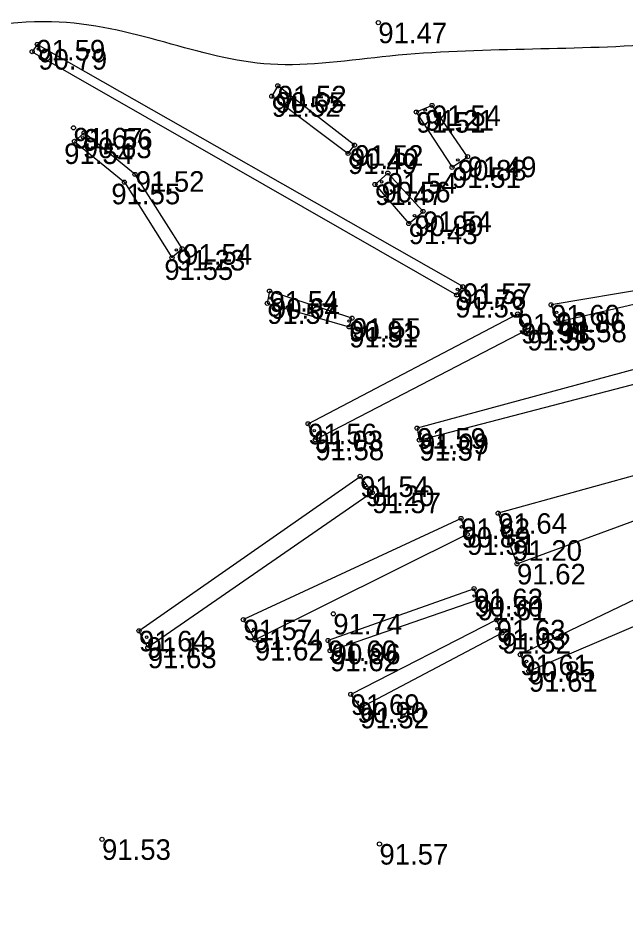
# Model space of a CAD drawing. Extents: x 316000 to 728450, y 314368 to 726000.
# Drawn here: x 725874.3 to 725985.1, y 315550.4 to 315715.2 of the extents above; entities that cross this region are included whole.
import ezdxf

# ---------------------------------------------------------------- set-up
doc = ezdxf.new("R2010")
doc.units = 0
for name, color, linetype in [('HIDG_ELEM_####_####_#', 7, 'Continuous'), ('HIDG_GRAV_####_####_#', 7, 'Continuous'), ('RELJ_AATZ_####_TKST_#', 7, 'Continuous'), ('RELJ_ELEM_####_####_#', 7, 'Continuous'), ('RELJ_HORZ_PAMT_####_#', 7, 'Continuous'), ('RELJ_NOGA_####_####_#', 7, 'Continuous')]:
    doc.layers.add(name, color=color, linetype=linetype)

msp = doc.modelspace()

# ---------------------------------------------------------------- linework, layer by layer
at = {"layer": 'HIDG_ELEM_####_####_#'}
for centre in [(725877.97, 315709.54), (725948.47, 315698.41), (725886.07, 315693.39), (725954.43, 315689.31), (725940.54, 315685.33), (725946.53, 315679.17), (725903.14, 315672.91), (725954.36, 315665.72), (725920.36, 315664.11), (725972.42, 315661.54), (725934.61, 315659.94), (725965.93, 315659.61), (725928.25, 315639.94), (725947.53, 315639.4), (725937.6, 315629.94), (725955.1, 315622.4), (725964.5, 315619.97), (725957.41, 315609.79), (725917.2, 315603.69), (725961.56, 315603.8), (725897.71, 315602.28), (725931.44, 315601.1), (725966.94, 315597.86), (725936.1, 315590.45)]:
    msp.add_circle(centre, 0.225, dxfattribs=at)
at = {"layer": 'HIDG_GRAV_####_####_#'}
for points in [[(725954.2, 315664.7), (725955.32, 315666.22), (725877.78, 315710.38), (725876.85, 315709.06), (725954.2, 315664.7)], [(725921.61, 315702.84), (725920.51, 315700.94), (725934.42, 315690.51), (725935.6, 315692.01), (725921.61, 315702.84)], [(725949.73, 315699.26), (725946.86, 315698.05), (725953.38, 315687.98), (725956.2, 315689.91), (725949.73, 315699.26)], [(725886.31, 315694.24), (725884.57, 315692.71), (725893.66, 315685.27), (725902.33, 315671.5), (725904.19, 315673.14), (725895.6, 315686.68), (725886.31, 315694.24)], [(725941.66, 315686.92), (725939.33, 315684.85), (725945.48, 315677.72), (725948.08, 315679.93), (725941.66, 315686.92)], [(725920.1, 315665.4), (725919.69, 315663.17), (725934.63, 315658.87), (725935.13, 315660.46), (725920.1, 315665.4)], [(725971.42, 315662.89), (725972.67, 315659.82), (725989.93, 315663.82), (725989.49, 315665.92), (725971.42, 315662.89)], [(725928.45, 315638.3), (725927.13, 315641.21), (725965.34, 315661.23), (725967.08, 315658.32), (725928.45, 315638.3)], [(725947, 315640.41), (725947.4, 315638.23), (725993.06, 315650.14), (725992.55, 315652.74), (725947, 315640.41)], [(725961.77, 315624.89), (725965.2, 315615.66), (725992.91, 315625.87), (726004, 315625.55), (726002.67, 315629.29), (726003.02, 315636.83), (726002.03, 315639.09), (725990.81, 315632.94), (725961.77, 315624.89)], [(725936.62, 315631.61), (725938.81, 315628.65), (725897.93, 315600.38), (725896.31, 315603.45), (725936.62, 315631.61)], [(725915.34, 315605.48), (725917.44, 315601.78), (725956.12, 315621.05), (725955.02, 315623.94), (725915.34, 315605.48)], [(725965.8, 315599.1), (725967.37, 315596.09), (726005.84, 315612.53), (726003.63, 315614.7), (726007.88, 315615.15), (726006.65, 315618.54), (726003.38, 315617.21), (725965.8, 315599.1)], [(725930.78, 315601.68), (725931.14, 315599.82), (725958.04, 315609.12), (725957.39, 315611.13), (725930.78, 315601.68)], [(725934.91, 315591.86), (725936.62, 315589.41), (725962.49, 315603.05), (725961.5, 315605.45), (725934.91, 315591.86)]]:
    msp.add_lwpolyline(points, dxfattribs=at)
at = {"layer": 'RELJ_ELEM_####_####_#'}
for centre in [(725939.93, 315714.36), (725877.78, 315710.38), (725876.85, 315709.06), (725921.61, 315702.84), (725920.51, 315700.94), (725946.86, 315698.05), (725949.73, 315699.26), (725884.38, 315695.17), (725886.31, 315694.24), (725884.57, 315692.71), (725935.6, 315692.01), (725934.42, 315690.51), (725956.2, 315689.91), (725953.38, 315687.98), (725895.6, 315686.68), (725941.66, 315686.92), (725893.66, 315685.27), (725939.33, 315684.85), (725948.08, 315679.93), (725945.48, 315677.72), (725904.19, 315673.14), (725902.33, 315671.5), (725920.1, 315665.4), (725955.32, 315666.22), (725954.2, 315664.7), (725919.69, 315663.17), (725971.42, 315662.89), (725935.13, 315660.46), (725965.34, 315661.23), (725934.63, 315658.87), (725967.08, 315658.32), (725972.67, 315659.82), (725927.13, 315641.21), (725947, 315640.41), (725928.45, 315638.3), (725947.4, 315638.23), (725936.62, 315631.61), (725938.81, 315628.65), (725955.02, 315623.94), (725961.77, 315624.89), (725956.12, 315621.05), (725965.2, 315615.66), (725957.39, 315611.13), (725958.04, 315609.12), (725931.72, 315606.54), (725915.34, 315605.48), (725961.5, 315605.45), (725896.31, 315603.45), (725962.49, 315603.05), (725917.44, 315601.78), (725930.78, 315601.68), (725897.93, 315600.38), (725931.14, 315599.82), (725965.8, 315599.1), (725967.37, 315596.09), (725934.91, 315591.86), (725936.62, 315589.41), (725889.58, 315565.42), (725940.14, 315564.56)]:
    msp.add_circle(centre, 0.375, dxfattribs=at)
at = {"layer": 'RELJ_HORZ_PAMT_####_#'}
msp.add_spline([(726116.34, 315699.09), (726105.94, 315702.69), (726040.13, 315715), (725990.82, 315710.42), (725942.03, 315708.25), (725920.28, 315706.77), (725880.37, 315714.51), (725859.05, 315708.68), (725859.05, 315672.66), (725851.26, 315613.97), (725853.47, 315568.9), (725841, 315555.79), (725885.56, 315509.63), (725935.94, 315461.49), (725983.42, 315406.25), (726032.86, 315360.51), (726082.85, 315311.19), (726122.23, 315248.76), (726137.05, 315229.29), (726180.19, 315183.1), (726194.52, 315168.27), (726211.91, 315146.93), (726212.51, 315143.16)], degree=3, dxfattribs=at)
at = {"layer": 'RELJ_NOGA_####_####_#'}
for points in [[(726259.12, 315084.51), (726262.72, 315089.26), (726261.56, 315090.84), (726260.2, 315092.42), (726257.29, 315095.53), (726218.91, 315136.38), (726180.31, 315176.84), (726128.67, 315229.97), (726063.7, 315298.11), (725999.9, 315366.09), (725937.21, 315432.09), (725876.35, 315495.23), (725810.58, 315563.08), (725744.7, 315632.91)], [(725740.86, 315626.98), (725805.54, 315558.12), (725870.39, 315491.15), (725932.8, 315426.8), (725994.98, 315360.84), (726059.66, 315292.12), (726075.75, 315275.46), (726092.08, 315259.04), (726108.47, 315242.67), (726124.69, 315226.14), (726193.27, 315154.03), (726250.06, 315092.6), (726256.32, 315085.83), (726258.82, 315084.29), (726259.12, 315084.51)]]:
    msp.add_spline(points, degree=3, dxfattribs=at)

# ---------------------------------------------------------------- texts
at = {"layer": 'RELJ_AATZ_####_TKST_#'}
for s, p in [('91.47', (725939.93, 315710.61)), ('91.59', (725877.62, 315707.46)), ('90.79', (725877.97, 315705.79)), ('90.65', (725921.19, 315697.92)), ('91.52', (725921.61, 315699.09)), ('91.52', (725920.51, 315697.19)), ('91.21', (725948.47, 315694.66)), ('91.54', (725949.73, 315695.51)), ('91.51', (725946.86, 315694.3)), ('91.67', (725884.38, 315691.42)), ('91.56', (725886.26, 315691.21)), ('90.63', (725886.07, 315689.64)), ('91.54', (725882.68, 315688.58)), ('91.52', (725935.6, 315688.26)), ('91.49', (725934.42, 315686.76)), ('90.40', (725934.75, 315687.67)), ('91.49', (725956.2, 315686.16)), ('90.88', (725954.43, 315685.56)), ('91.52', (725895.7, 315683.52)), ('91.54', (725941.66, 315683.17)), ('91.51', (725953.38, 315684.23)), ('91.55', (725891.28, 315681.23)), ('90.56', (725940.54, 315681.58)), ('91.47', (725939.33, 315681.1)), ('90.90', (725946.53, 315675.42)), ('91.54', (725948.08, 315676.18)), ('91.43', (725945.48, 315673.97)), ('91.54', (725904.36, 315670.21)), ('91.23', (725903.14, 315669.16)), ('91.55', (725900.94, 315667.44)), ('91.54', (725920.1, 315661.65)), ('90.76', (725954.36, 315661.97)), ('91.57', (725955.35, 315663.06)), ('90.64', (725920.36, 315660.36)), ('91.53', (725953.96, 315660.58)), ('91.57', (725919.69, 315659.42)), ('91.60', (725971.42, 315659.14)), ('91.55', (725935.13, 315656.71)), ('91.58', (725965.34, 315657.48)), ('90.86', (725972.42, 315657.79)), ('90.91', (725934.61, 315656.19)), ('91.51', (725934.63, 315655.12)), ('90.98', (725965.93, 315655.86)), ('91.58', (725972.67, 315656.07)), ('91.55', (725967.08, 315654.57)), ('91.56', (725927.13, 315637.46)), ('91.03', (725928.25, 315636.19)), ('91.59', (725947, 315636.66)), ('91.09', (725947.53, 315635.65)), ('91.58', (725928.45, 315634.55)), ('91.57', (725947.4, 315634.48)), ('91.54', (725936.62, 315627.86)), ('91.20', (725937.6, 315626.19)), ('91.57', (725938.81, 315624.9)), ('91.64', (725961.77, 315621.14)), ('91.62', (725955.02, 315620.19)), ('90.89', (725955.1, 315618.65)), ('91.51', (725956.12, 315617.3)), ('91.20', (725964.5, 315616.22)), ('91.62', (725965.2, 315611.91)), ('91.62', (725957.39, 315607.38)), ('90.50', (725957.41, 315606.04)), ('91.61', (725958.04, 315605.37)), ('91.74', (725931.72, 315602.79)), ('91.57', (725915.34, 315601.73)), ('91.63', (725961.5, 315601.7)), ('91.64', (725896.31, 315599.7)), ('91.24', (725917.2, 315599.94)), ('91.03', (725961.56, 315600.05)), ('91.52', (725962.49, 315599.3)), ('91.13', (725897.71, 315598.53)), ('91.62', (725917.44, 315598.03)), ('91.60', (725930.78, 315597.93)), ('90.96', (725931.44, 315597.35)), ('91.63', (725897.93, 315596.63)), ('91.62', (725931.14, 315596.07)), ('91.61', (725965.8, 315595.35)), ('90.85', (725966.94, 315594.11)), ('91.61', (725967.37, 315592.34)), ('91.69', (725934.91, 315588.11)), ('90.90', (725936.1, 315586.7)), ('91.52', (725936.62, 315585.66)), ('91.53', (725889.58, 315561.67)), ('91.57', (725940.14, 315560.81))]:
    msp.add_text(s, height=3.75, dxfattribs=at).set_placement(p)

doc.saveas('drawing.dxf')
